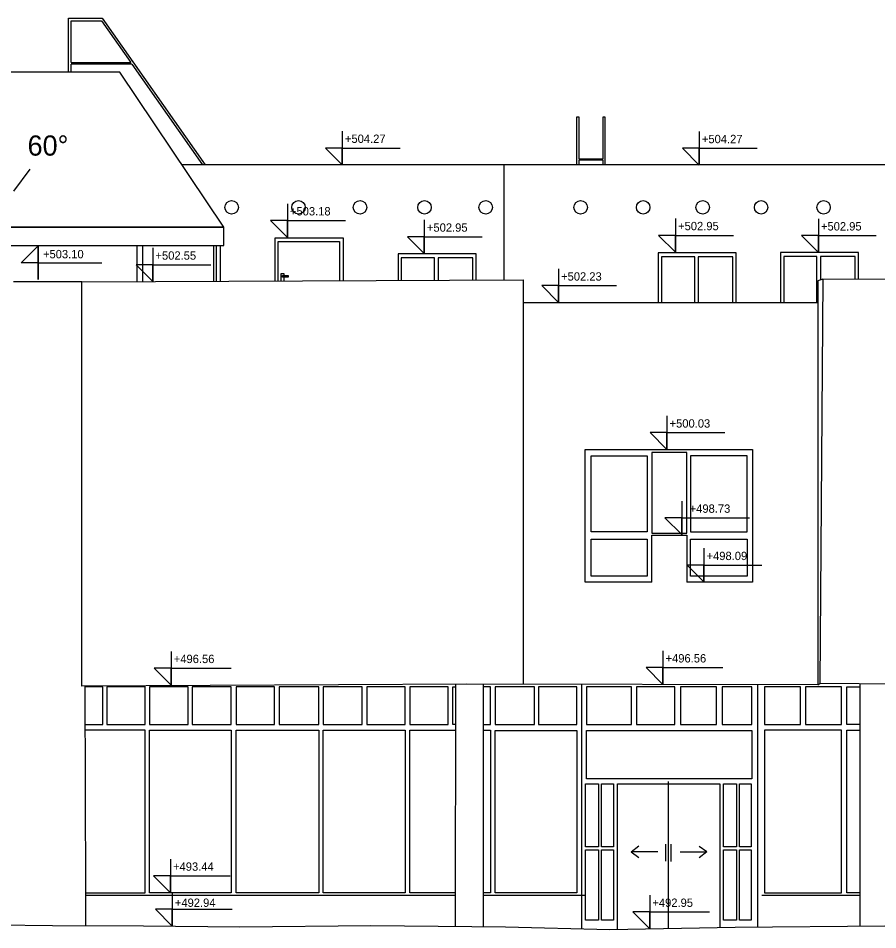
# Model space of a CAD drawing. Extents: x 3.3 to 94, y 492.8 to 514.5.
# Drawn here: x 29.8 to 42.57, y 492.91 to 506.46 of the extents above; entities that cross this region are included whole.
import ezdxf

# ---------------------------------------------------------------- set-up
doc = ezdxf.new("R2010")
doc.units = 0
for name, color, linetype in [('dvere', 7, 'Continuous'), ('okap', 7, 'Continuous'), ('okna', 7, 'Continuous'), ('strecha_sikma', 7, 'Continuous'), ('teren', 7, 'Continuous'), ('zakl_tenka', 7, 'Continuous'), ('zakl_tlusta', 7, 'Continuous'), ('zebrik', 7, 'Continuous'), ('znaceni', 7, 'Continuous')]:
    doc.layers.add(name, color=color, linetype=linetype)

msp = doc.modelspace()

# ---------------------------------------------------------------- linework, layer by layer
at = {"layer": 'dvere'}
for p, q in [((39.458, 495.113), (39.458, 492.924)), ((39.418, 494.181), (39.418, 493.928)), ((39.499, 494.179), (39.499, 493.926))]:
    msp.add_line(p, q, dxfattribs=at)
for points in [[(33.667, 502.555), (33.667, 503.138), (34.577, 503.138), (34.577, 502.559)], [(33.711, 502.555), (33.711, 502.664), (33.751, 502.664), (33.751, 502.633)], [(33.751, 502.611), (33.751, 502.556)], [(38.705, 492.911), (38.705, 495.077), (40.227, 495.077), (40.227, 492.938)]]:
    msp.add_lwpolyline(points, dxfattribs=at)
msp.add_lwpolyline([(33.727, 502.633), (33.815, 502.633), (33.815, 502.611), (33.727, 502.611)], close=True, dxfattribs=at)
at = {"layer": 'okap'}
msp.add_line((32.805, 503.081), (32.805, 502.551), dxfattribs=at)
for points in [[(25.326, 503.354), (22.066, 503.354), (22.066, 503.081), (32.859, 503.081), (32.859, 503.354), (28.259, 503.354)], [(31.566, 503.081), (31.566, 502.546)], [(31.653, 502.546), (31.653, 503.081)], [(32.75, 502.551), (32.75, 503.081)]]:
    msp.add_lwpolyline(points, dxfattribs=at)
at = {"layer": 'okna'}
for p, q in [((30.794, 496.532), (30.801, 493.458)), ((38.172, 496.556), (38.172, 492.919)), ((40.787, 496.55), (40.787, 492.946))]:
    msp.add_line(p, q, dxfattribs=at)
for points in [[(35.988, 502.566), (35.988, 502.895), (35.494, 502.895), (35.494, 502.563)], [(36.556, 502.568), (36.556, 502.895), (36.04, 502.895), (36.04, 502.566)], [(39.853, 502.23), (39.853, 502.912), (39.359, 502.912), (39.359, 502.23)], [(40.421, 502.23), (40.421, 502.912), (39.905, 502.912), (39.905, 502.23)], [(41.67, 502.23), (41.67, 502.916), (41.176, 502.916), (41.176, 502.23)], [(42.239, 502.577), (42.239, 502.916), (41.722, 502.916), (41.722, 502.568)], [(30.796, 495.961), (31.06, 495.961), (31.06, 496.518), (30.794, 496.518)], [(36.3, 495.961), (36.258, 495.961), (36.258, 496.518), (36.301, 496.518)], [(36.709, 495.961), (36.819, 495.961), (36.819, 496.518), (36.709, 496.518)], [(42.305, 495.961), (42.111, 495.961), (42.111, 496.518), (42.305, 496.518)], [(30.801, 493.458), (31.69, 493.458), (31.69, 495.875), (30.796, 495.875)], [(36.296, 493.456), (35.621, 493.456), (35.621, 495.875), (36.3, 495.875)], [(36.709, 495.875), (36.819, 495.875), (36.819, 493.456), (36.709, 493.456)], [(42.305, 493.457), (42.111, 493.457), (42.111, 495.878), (42.305, 495.878)]]:
    msp.add_lwpolyline(points, dxfattribs=at)
for points in [[(39.218, 498.804), (39.736, 498.804), (39.736, 500.003), (39.218, 500.003)], [(39.149, 498.822), (38.315, 498.822), (38.315, 499.952), (39.149, 499.952)], [(39.792, 498.822), (40.633, 498.822), (40.633, 499.952), (39.792, 499.952)], [(38.315, 498.717), (39.149, 498.717), (39.149, 498.166), (38.315, 498.166)], [(39.792, 498.717), (40.633, 498.717), (40.633, 498.166), (39.792, 498.166)], [(31.69, 496.518), (31.121, 496.518), (31.121, 495.961), (31.69, 495.961)], [(32.33, 496.518), (31.755, 496.518), (31.755, 495.961), (32.33, 495.961)], [(32.965, 496.518), (32.387, 496.518), (32.387, 495.961), (32.965, 495.961)], [(33.609, 496.518), (33.042, 496.518), (33.042, 495.961), (33.609, 495.961)], [(34.27, 496.518), (33.679, 496.518), (33.679, 495.961), (34.27, 495.961)], [(34.912, 496.518), (34.332, 496.518), (34.332, 495.961), (34.912, 495.961)], [(35.554, 496.518), (34.98, 496.518), (34.98, 495.961), (35.554, 495.961)], [(36.191, 496.518), (35.621, 496.518), (35.621, 495.961), (36.191, 495.961)], [(37.472, 496.518), (36.89, 496.518), (36.89, 495.961), (37.472, 495.961)], [(38.104, 496.518), (37.532, 496.518), (37.532, 495.961), (38.104, 495.961)], [(38.915, 496.518), (38.244, 496.518), (38.244, 495.961), (38.915, 495.961)], [(39.559, 496.518), (38.987, 496.518), (38.987, 495.961), (39.559, 495.961)], [(40.178, 496.518), (39.642, 496.518), (39.642, 495.961), (40.178, 495.961)], [(40.704, 496.518), (40.262, 496.518), (40.262, 495.961), (40.704, 495.961)], [(41.425, 496.518), (40.889, 496.518), (40.889, 495.961), (41.425, 495.961)], [(42.035, 496.518), (41.498, 496.518), (41.498, 495.961), (42.035, 495.961)], [(31.755, 495.875), (32.965, 495.875), (32.965, 493.458), (31.755, 493.458)], [(33.042, 495.875), (34.27, 495.875), (34.27, 493.458), (33.042, 493.458)], [(34.332, 495.875), (35.554, 495.875), (35.554, 493.458), (34.332, 493.458)], [(36.89, 495.871), (38.104, 495.871), (38.104, 493.456), (36.89, 493.456)], [(38.244, 495.871), (40.704, 495.871), (40.704, 495.151), (38.244, 495.151)], [(42.035, 495.878), (40.889, 495.878), (40.889, 493.457), (42.035, 493.457)], [(38.233, 495.077), (38.425, 495.077), (38.425, 494.143), (38.233, 494.143)], [(38.47, 495.077), (38.646, 495.077), (38.646, 494.143), (38.47, 494.143)], [(40.282, 495.077), (40.473, 495.077), (40.473, 494.143), (40.282, 494.143)], [(40.518, 495.077), (40.694, 495.077), (40.694, 494.143), (40.518, 494.143)], [(38.233, 494.097), (38.425, 494.097), (38.425, 493.051), (38.233, 493.051)], [(38.47, 494.097), (38.646, 494.097), (38.646, 493.051), (38.47, 493.051)], [(40.282, 494.097), (40.473, 494.097), (40.473, 493.051), (40.282, 493.051)], [(40.518, 494.097), (40.694, 494.097), (40.694, 493.051), (40.518, 493.051)]]:
    msp.add_lwpolyline(points, close=True, dxfattribs=at)
at = {"layer": 'strecha_sikma'}
for p, q in [((31.313, 505.658), (23.58, 505.658)), ((32.859, 503.354), (31.313, 505.658)), ((28.259, 503.354), (32.859, 503.354))]:
    msp.add_line(p, q, dxfattribs=at)
at = {"layer": 'teren'}
for p, q in [((30.314, 492.969), (28.806, 492.984)), ((31.665, 492.962), (30.314, 492.969)), ((33.096, 492.948), (31.665, 492.962)), ((35.041, 492.965), (33.096, 492.948)), ((37.04, 492.946), (35.041, 492.965)), ((38.593, 492.909), (37.04, 492.946)), ((40.456, 492.943), (38.593, 492.909)), ((42.678, 492.964), (40.456, 492.943))]:
    msp.add_line(p, q, dxfattribs=at)
at = {"layer": 'zakl_tenka'}
for p, q in [((47.349, 504.278), (32.24, 504.278)), ((37.016, 504.278), (37.016, 502.57)), ((32.705, 503.081), (32.705, 502.551)), ((30.75, 502.542), (37.303, 502.572)), ((37.303, 502.572), (37.303, 496.558)), ((41.755, 502.58), (41.682, 502.553)), ((41.682, 502.553), (41.682, 496.548)), ((41.755, 502.58), (41.713, 496.567)), ((48.295, 502.539), (41.755, 502.58)), ((30.75, 502.542), (29.735, 502.542)), ((30.75, 496.532), (30.75, 502.542)), ((41.682, 502.23), (37.303, 502.23)), ((36.469, 496.56), (30.75, 496.532)), ((36.301, 496.559), (36.294, 492.953)), ((41.682, 496.548), (36.469, 496.56)), ((36.709, 496.56), (36.709, 492.949)), ((41.682, 496.548), (41.713, 496.567)), ((48.253, 496.536), (41.713, 496.567)), ((42.305, 496.56), (42.305, 492.96)), ((30.801, 493.458), (30.801, 492.966)), ((36.295, 493.419), (30.801, 493.419)), ((38.233, 493.419), (36.709, 493.419)), ((42.305, 493.419), (40.849, 493.419))]:
    msp.add_line(p, q, dxfattribs=at)
for points in [[(40.47, 502.23), (40.47, 502.971), (39.312, 502.971), (39.312, 502.23)], [(42.287, 502.577), (42.287, 502.975), (41.13, 502.975), (41.13, 502.23)], [(36.605, 502.568), (36.605, 502.954), (35.447, 502.954), (35.447, 502.563)], [(39.218, 498.077), (38.227, 498.077), (38.227, 500.046), (40.714, 500.046), (40.714, 498.077), (39.736, 498.077)], [(39.218, 498.077), (39.218, 498.775), (39.736, 498.775), (39.736, 498.077)]]:
    msp.add_lwpolyline(points, dxfattribs=at)
for centre in [(32.974, 503.647), (33.967, 503.647), (34.881, 503.647), (35.839, 503.647), (36.748, 503.647), (38.159, 503.647), (39.088, 503.647), (39.972, 503.647), (40.84, 503.647), (41.768, 503.647)]:
    msp.add_circle(centre, 0.1, dxfattribs=at)
at = {"layer": 'zakl_tlusta'}
msp.add_lwpolyline([(33.621, 502.555), (33.621, 503.196), (34.629, 503.196), (34.629, 502.56)], dxfattribs=at)
at = {"layer": 'zebrik'}
for p, q in [((30.551, 505.658), (30.551, 506.458)), ((30.551, 506.458), (31.05, 506.458)), ((30.59, 505.798), (30.59, 506.422)), ((30.59, 506.422), (31.038, 506.422)), ((31.038, 506.422), (31.475, 505.798)), ((31.05, 506.458), (32.579, 504.278)), ((30.59, 505.658), (30.59, 505.773)), ((31.493, 505.773), (32.541, 504.278))]:
    msp.add_line(p, q, dxfattribs=at)
for points in [[(30.59, 505.798), (31.475, 505.798)], [(31.493, 505.773), (30.59, 505.773)], [(38.104, 504.278), (38.104, 504.991), (38.13, 504.991), (38.13, 504.366)], [(38.491, 504.366), (38.491, 504.991), (38.517, 504.991), (38.517, 504.278)], [(38.13, 504.366), (38.491, 504.366)], [(38.13, 504.348), (38.13, 504.278)], [(38.491, 504.348), (38.13, 504.348)], [(38.491, 504.278), (38.491, 504.348)]]:
    msp.add_lwpolyline(points, dxfattribs=at)
at = {"layer": 'znaceni'}
for p, q in [((34.618, 504.779), (34.618, 504.279)), ((39.921, 504.776), (39.921, 504.276)), ((34.618, 504.529), (34.368, 504.529)), ((34.368, 504.529), (34.618, 504.279)), ((34.618, 504.279), (34.618, 504.529)), ((34.618, 504.529), (35.479, 504.529)), ((39.921, 504.526), (39.671, 504.526)), ((39.671, 504.526), (39.921, 504.276)), ((39.921, 504.276), (39.921, 504.526)), ((39.921, 504.526), (40.782, 504.526)), ((29.739, 503.889), (29.979, 504.216)), ((33.802, 503.701), (33.802, 503.201)), ((33.802, 503.451), (33.552, 503.451)), ((33.552, 503.451), (33.802, 503.201)), ((33.802, 503.201), (33.802, 503.451)), ((33.802, 503.451), (34.663, 503.451)), ((35.836, 503.46), (35.836, 502.96)), ((39.567, 503.481), (39.567, 502.981)), ((41.69, 503.477), (41.69, 502.977)), ((39.567, 503.231), (39.317, 503.231)), ((39.317, 503.231), (39.567, 502.981)), ((39.567, 502.981), (39.567, 503.231)), ((39.567, 503.231), (40.429, 503.231)), ((35.836, 503.21), (35.586, 503.21)), ((35.586, 503.21), (35.836, 502.96)), ((35.836, 502.96), (35.836, 503.21)), ((35.836, 503.21), (36.697, 503.21)), ((41.69, 503.227), (41.44, 503.227)), ((41.44, 503.227), (41.69, 502.977)), ((41.69, 502.977), (41.69, 503.227)), ((41.69, 503.227), (42.551, 503.227)), ((29.848, 502.824), (30.098, 503.074)), ((30.098, 503.074), (30.098, 502.574)), ((30.098, 502.574), (30.098, 503.074)), ((30.098, 503.074), (30.098, 502.824)), ((31.804, 503.043), (31.804, 502.543)), ((30.098, 502.824), (29.848, 502.824)), ((30.098, 502.824), (29.848, 502.824)), ((30.098, 502.574), (30.098, 502.824)), ((30.098, 502.824), (31.044, 502.824)), ((30.098, 502.824), (31.044, 502.824)), ((31.804, 502.793), (31.554, 502.793)), ((31.554, 502.793), (31.804, 502.543)), ((31.804, 502.543), (31.804, 502.793)), ((31.804, 502.793), (32.665, 502.793)), ((37.83, 502.733), (37.83, 502.233)), ((37.83, 502.483), (37.58, 502.483)), ((37.58, 502.483), (37.83, 502.233)), ((37.83, 502.233), (37.83, 502.483)), ((37.83, 502.483), (38.691, 502.483)), ((39.441, 500.548), (39.441, 500.048)), ((39.441, 500.298), (39.191, 500.298)), ((39.191, 500.298), (39.441, 500.048)), ((39.441, 500.048), (39.441, 500.298)), ((39.441, 500.298), (40.302, 500.298)), ((39.661, 499.282), (39.661, 498.782)), ((39.661, 499.032), (39.411, 499.032)), ((39.411, 499.032), (39.661, 498.782)), ((39.661, 498.782), (39.661, 499.032)), ((39.661, 499.032), (40.666, 499.032)), ((39.99, 498.579), (39.99, 498.079)), ((39.99, 498.329), (39.74, 498.329)), ((39.74, 498.329), (39.99, 498.079)), ((39.99, 498.079), (39.99, 498.329)), ((39.99, 498.329), (40.852, 498.329)), ((32.075, 497.047), (32.075, 496.547)), ((39.382, 497.056), (39.382, 496.556)), ((32.075, 496.797), (31.825, 496.797)), ((31.825, 496.797), (32.075, 496.547)), ((32.075, 496.547), (32.075, 496.797)), ((32.075, 496.797), (32.965, 496.797)), ((39.382, 496.806), (39.132, 496.806)), ((39.132, 496.806), (39.382, 496.556)), ((39.382, 496.556), (39.382, 496.806)), ((39.382, 496.806), (40.271, 496.806)), ((38.907, 494.069), (39.022, 494.154)), ((39.304, 494.069), (38.907, 494.069)), ((38.907, 494.069), (39.022, 493.985)), ((39.638, 494.065), (40.035, 494.065)), ((40.035, 494.065), (39.92, 494.149)), ((40.035, 494.065), (39.92, 493.98)), ((32.064, 493.96), (32.064, 493.46)), ((32.064, 493.71), (31.814, 493.71)), ((31.814, 493.71), (32.064, 493.46)), ((32.064, 493.46), (32.064, 493.71)), ((32.064, 493.71), (32.954, 493.71)), ((32.091, 493.464), (32.091, 492.964)), ((39.185, 493.423), (39.185, 492.923)), ((32.091, 493.214), (31.841, 493.214)), ((31.841, 493.214), (32.091, 492.964)), ((32.091, 492.964), (32.091, 493.214)), ((32.091, 493.214), (32.981, 493.214)), ((39.185, 493.173), (38.935, 493.173)), ((38.935, 493.173), (39.185, 492.923)), ((39.185, 492.923), (39.185, 493.173)), ((39.185, 493.173), (40.075, 493.173))]:
    msp.add_line(p, q, dxfattribs=at)

# ---------------------------------------------------------------- texts
for s, height, p in [('60°', 0.3, (29.942, 504.416)), ('+504.27', 0.124, (34.657, 504.605)), ('+504.27', 0.124, (39.96, 504.601)), ('+503.18', 0.124, (33.84, 503.527)), ('+502.95', 0.124, (35.875, 503.285)), ('+502.95', 0.124, (39.606, 503.307)), ('+502.95', 0.124, (41.729, 503.303)), ('+503.10', 0.124, (30.171, 502.89)), ('+502.55', 0.124, (31.842, 502.869)), ('+502.23', 0.124, (37.868, 502.558)), ('+500.03', 0.124, (39.48, 500.373)), ('+498.73', 0.124, (39.778, 499.107)), ('+498.09', 0.124, (40.029, 498.404)), ('+496.56', 0.124, (32.114, 496.873)), ('+496.56', 0.124, (39.42, 496.882)), ('+493.44', 0.124, (32.103, 493.786)), ('+492.94', 0.124, (32.13, 493.249)), ('+492.95', 0.124, (39.224, 493.249))]:
    msp.add_text(s, height=height, dxfattribs=at).set_placement(p)

doc.saveas('drawing.dxf')
